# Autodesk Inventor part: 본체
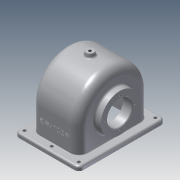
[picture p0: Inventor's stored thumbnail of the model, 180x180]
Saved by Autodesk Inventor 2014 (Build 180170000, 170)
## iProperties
Created: 2015-09
Part Number: 본체
Material: 알루미늄 6061
Document SubType Name: Modeling
Designer: sda3
Density: 2.71 g/cm^3
Appearance: 알루미늄 - 평지
Mass: 723.372 g
Surface Area: 889.376 cm^2
Volume: 266.927 cm^3
Author: sda3
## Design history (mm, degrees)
sketch "스케치2"
  geometry: L1 (52, -70)-(-52, -70); L2 (-52, -70)-(-52, 70); L3 (-52, 70)-(52, 70); L4 (52, 70)-(52, -70); L5 (-52, 70)-(52, -70); 2 further points
  constraints: 10 end point, 2 parallel, 1 coincident, 1 horizontal, 1 midpoint, 1 perpendicular
  dimensions: "d0" = 104 distance of L2.end L3.end; "d1" = 140 distance of L3.end L1.start
extrude "돌출1" new body sketch "스케치2" distance "d2" = 7; taper "d3" = 0 deg
sketch "스케치3"
  geometry: L1 (-38.5, 57)-(38.5, 57); L2 (38.5, 57)-(38.5, -57); L3 (38.5, -57)-(-38.5, -57); L4 (-38.5, -57)-(-38.5, 57); L5 (38.5, -57)-(-38.5, 57); 2 further points
  constraints: 10 end point, 2 parallel, 1 coincident, 1 horizontal, 1 midpoint, 1 perpendicular
  dimensions: "d4" = 77 distance of L2.end L3.end; "d5" = 114 distance of L3.end L1.start
extrude "돌출2" join sketch "스케치3" distance "d6" = 40; taper "d7" = 0 deg
sketch "스케치4"
  geometry: L1 (7, 57)-(7, -57) reference; L2 (7, 57)-(47, 57) reference; L3 (47, -57)-(47, 57) reference; L4 (7, -57)-(47, -57) reference; L5 (47, 57)-(47, -57); A1 r 57 centre (47, 0) between (47, -57) and (47, 57); 1 further point
  constraints: 2 end point, 2 point on circle, 1 centre point, 1 collinear
  dimensions: "d8" = 57 radius of A1
extrude "돌출3" join sketch "스케치4" stored distance "d9" = 77; taper "d10" = 0 deg
sketch "스케치5"
  geometry: L1 (-38.5, 47)-(38.5, 47) reference; L2 (38.5, 47)-(38.5, 47) reference; L3 (38.5, 47)-(-38.5, 47) reference; L4 (-38.5, 47)-(-38.5, 47) reference; L5 (-38.5, 7)-(38.5, 7) reference; L6 (-38.5, 7)-(-38.5, 47) reference; L7 (38.5, 47)-(-38.5, 47) reference; L8 (38.5, 7)-(38.5, 47) reference; L9 (-38.5, 47)-(38.5, 47); L10 (-38.5, 104)-(-38.5, 47) reference; L11 (-38.5, 104)-(38.5, 104) reference; L12 (38.5, 47)-(38.5, 104) reference; L13 (-33.5, 47)-(-33.5, 98); L14 (-33.5, 98)-(33.5, 98); L15 (33.5, 98)-(33.5, 47); 1 further point
  constraints: 8 end point, 2 perpendicular, 2 point on line, 1 collinear, 1 parallel
  dimensions: "d11" = 5 distance between parallel lines of L12 L15; "d12" = 5 distance between parallel lines of L10 L13; "d13" = 6 distance between parallel lines of L11 L14
revolve "회전1" sketch "스케치5" stored, may be unused: angle "d14" = 90 deg
sketch "스케치6"
  geometry: L1 (-33.5, 51)-(-33.5, -51) reference; L2 (33.5, 19.799)-(33.5, -19.799) reference; L3 (33.5, -19.799)-(-33.5, -19.799) reference; L4 (-33.5, -19.799)-(-33.5, 19.799) reference; L5 (-33.5, 19.799)-(33.5, 19.799) reference; L6 (-52, -70)-(52, -70) reference; L7 (52, -70)-(52, 70) reference; L8 (52, 70)-(-52, 70) reference; L9 (-52, 70)-(-52, -70) reference; L10 (33.5, 51)-(-33.5, 51) reference; L11 (33.5, 51)-(33.5, -51) reference; L12 (33.5, -51)-(-33.5, -51) reference; L13 (-33.5, 51)-(33.5, 51); L14 (33.5, 51)-(33.5, -51); L15 (33.5, -51)-(-33.5, -51); L16 (-33.5, -51)-(-33.5, 51); 1 further point
  constraints: 8 end point, 2 parallel, 1 horizontal, 1 perpendicular
extrude "돌출4" cut sketch "스케치6" distance "d15" = 47; taper "d16" = 0 deg
sketch "스케치7"
  geometry: C1 r 31 at (57, 40); A1 r 57 centre (57, 40) between (114, 40) and (0, 40) reference; 1 further point
  constraints: 1 centre point, 1 coincident
  dimensions: "d17" = 62 diameter of C1
extrude "돌출5" join sketch "스케치7" distance "d18" = 10; taper "d19" = 0 deg
sketch "스케치8"
  geometry: C1 r 31 at (0, 0) reference; 2 further points
  constraints: 1 coincident
hole "구멍1" sketch "스케치8" at (0, 0) diameter "d20" = 40; stored, may be unused: countersink angle "d24" = 90 deg, drill point angle "d26" = 118 deg; dims "d21" = 6, "d22" = 4, "d23" = 2, "d25" = 8
sketch "스케치9"
  geometry: L1 (-33.5, 47)-(33.5, 47) reference; L2 (-38.5, 104)-(-38.5, 47) reference; L3 (33.5, 47)-(-38.5, 47); L4 (-19.5, 47)-(-19.5, 75); L5 (-33.5, 98)-(-33.5, 47) reference; L6 (-19.5, 75)-(-33.5, 86.747); L7 (-38.5, 84.416)-(-33.237, 80); L8 (-33.237, 80)-(-35.5, 80); L9 (-35.5, 80)-(-35.5, 47); L10 (48.5, 16)-(48.5, 78) reference; L11 (-38.5, 84.416)-(-38.5, 47); L12 (-33.5, 86.747)-(-38.5, 84.416); 1 further point
  constraints: 16 end point, 4 perpendicular, 4 point on line, 1 collinear, 1 parallel
  dimensions: "d27" = 84 distance between parallel lines of L9 L10; "d28" = 28 distance from line of L1 L4.end; "d29" = 50 deg angle of L4 L6; "d30" = 5 distance between parallel lines of L6 L7; "d31" = 66 diameter of L8 L3; "d32" = 16 distance between parallel lines of L9 L4
revolve "회전2" stored, may be unused: angle "d33" = 90 deg
revolve "회전3" stored, may be unused: angle "d34" = 90 deg
sketch "스케치11"
  geometry: C1 r 33 at (0, 0) reference; 2 further points
  constraints: 1 coincident
hole "구멍2" sketch "스케치11" at (0, 0) diameter "d35" = 40; stored, may be unused: countersink angle "d39" = 90 deg, drill point angle "d41" = 118 deg; dims "d36" = 6, "d37" = 4, "d38" = 2, "d40" = 8
node "작업 평면1"
sketch "스케치12"
  geometry: C1 r 6 at (0, 0); 1 further point
  constraints: 1 centre point, 1 coincident
  dimensions: "d43" = 12 diameter of C1
extrude "돌출6" join sketch "스케치12" stored distance "d44" = 10; taper "d45" = 10 deg
chamfer "모따기1" distance "d46" = 1; stored, may be unused: second distance "d47" = 2, angle "d48" = 45 deg
fillet "모깎기1" dims "d49" = 7, "d50" = 9, "d51" = 14, "d52" = 3, "d53" = 0.5
sketch "스케치13"
  geometry: L1 (-44, 62)-(44, 62); L2 (44, 62)-(44, -62); L3 (44, -62)-(-44, -62); L4 (-44, -62)-(-44, 62); L5 (44, -62)-(-44, 62); 8 further points
  constraints: 10 end point, 5 coincident, 3 midpoint, 2 parallel, 1 horizontal, 1 perpendicular
  dimensions: "d54" = 124 distance of L1.end L2.end; "d55" = 88 distance of L1.start L1.end
hole "구멍3" sketch "스케치13" at (-44, 62), (44, 62), (44, -62), (-44, -62), (0, -62), (0, 62) diameter "d56" = 5; stored, may be unused: countersink angle "d60" = 90 deg, drill point angle "d62" = 118 deg; dims "d57" = 6, "d58" = 4, "d59" = 2, "d61" = 8
fillet "모깎기2" dims "d63" = 1, "d100" = 3
sketch "스케치14"
  geometry: L1 (0, 0)-(0, 24); L2 (0, 0)-(-24, 0); L3 (0, 0)-(0, -24); L4 (0, 0)-(24, 0); C1 r 31 at (0, 0) reference; C2 r 21 at (0, 0) reference; 5 further points
  constraints: 8 end point, 4 coincident, 1 vertical, 17 other
  dimensions: "d64" = 24 distance of L1.start L1.end; "d67" = 360 deg dimension on C1.centre L1.end (derived)
hole "구멍4" sketch "스케치14" at (0, 24), (-24, 0), (0, -24), (24, 0) diameter "d69" = 2.459; stored, may be unused: countersink angle "d73" = 90 deg, drill point angle "d75" = 118 deg; dims "d70" = 6, "d71" = 4, "d72" = 2, "d74" = 8
sketch "스케치15"
  geometry: L1 (0, 0)-(0, 28); C1 r 33 at (0, 0) reference; C2 r 21 at (0, 0) reference; 5 further points
  constraints: 2 end point, 1 coincident, 1 vertical, 5 other
  dimensions: "d76" = 28 distance of L1.start L1.end; "d79" = 360 deg dimension on C1.centre point (0, 28) (derived)
hole "구멍5" sketch "스케치15" at (0, 28), (-28, 0), (0, -28), (28, 0) diameter "d81" = 2.459; stored, may be unused: countersink angle "d85" = 90 deg, drill point angle "d87" = 118 deg; dims "d82" = 7, "d83" = 4, "d84" = 2, "d86" = 9
sketch "스케치16"
  geometry: C1 r 6 at (0, 0) reference; 1 further point
  constraints: 1 coincident
hole "구멍6" sketch "스케치16" at (0, 0) diameter "d88" = 4.459; stored, may be unused: countersink angle "d92" = 90 deg, drill point angle "d94" = 118 deg; dims "d89" = 7, "d90" = 4, "d91" = 2, "d93" = 9
sketch "스케치17"
  geometry: L1 (0, -39)-(0, 0) reference; L2 (24.5, -47)-(24.5, -17); L3 (-0.387, -13.398)-(49.387, -13.398); L4 (49.387, -13.398)-(49.387, -20.602); L5 (49.387, -20.602)-(-0.387, -20.602); L6 (-0.387, -20.602)-(-0.387, -13.398); L7 (-0.387, -13.398)-(49.387, -20.602)
  constraints: 4 end point, 1 horizontal, 1 midpoint, 1 parallel, 2 other
  dimensions: "d95" = 30 distance of L2.end L2.start; "d96" = 49.77477 distance of L4.end L5.end; "d97" = 7.20489 distance of L3.end L4.end
feature "엠보싱1" sketch "스케치17" dims "d0" = 104, "d1" = 140, "d8" = 57, "d98" = 0.5, "d99" = 0
node "솔리드1"
node "투영된 루프1"
node "투영된 루프2"
node "투영된 루프3"
node "투영된 루프4"
